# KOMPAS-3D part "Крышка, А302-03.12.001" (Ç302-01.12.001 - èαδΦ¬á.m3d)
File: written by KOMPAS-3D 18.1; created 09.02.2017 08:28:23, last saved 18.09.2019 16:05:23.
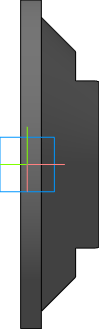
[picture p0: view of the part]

Document properties: Автор: Милов; Организация: Милов; Полное имя файла: D:\Мембранные насосы\Мембранный электропривод\А302-00.00.000 - ASTRA-302 (МЭ200)\3Д ПВХ\А302-01.12.001 - Крышка.m3d

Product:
- Part/product: Крышка  | designation А302-03.12.001
    Материал: Поливинилхлорид (density 1350 kg/m3)
    Масса: 2.71786
    Раздел спецификации: Детали
    Форматы листов документа: 2xA3
    Примечание: @100~)2xA3
    source file: ..\Чертежи Полипропилен\А302-03.12.001 - Крышка.cdw
- Part/product: Крышка  | designation А302-01.12.001
    Материал: Поливинилхлорид (density 1350 kg/m3)
    Масса: 2.45398
    Раздел спецификации: Детали
    Форматы листов документа: 2xA3
    Примечание: @100~)2xA3
    source file: А302-01.12.001 - Крышка.cdw
- Part/product: Крышка  | designation А302-02.12.001
    Материал: Поливинилхлорид (density 1350 kg/m3)
    Масса: 2.64473
    Раздел спецификации: Детали
    Форматы листов документа: 2xA3
    Примечание: @100~)2xA3
    source file: ..\Чертежи ПВХ\А302-02.12.001 - Крышка.cdw, А302-02.00.000 - ASTRA-302 (МЭ200)\А302-02.12.001 - Крышка.cdw

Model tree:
1. Эскиз:24
2. Операция вращения:2
     Угол 1 = 360
3. Эскиз:26  (with: Операция вращения:2)
4. Вырезать элемент выдавливания:1
     Расстояние 1 = 19
5. Массив по концентрической сетке:2  (with: Вырезать элемент выдавливания:1, Эскиз:26)  (12 pattern instances)
     Шаг 2 = 360
6. Фаска:1
     Угол = 45; Длина 1 = 0.5; Длина 2 = 0.5
7. Скругление:3  (with: Операция вращения:2)
     Радиус = 6
8. Эскиз:29
9. Вырезать элемент выдавливания:2
     Расстояние 1 = 47.5
10. Эскиз:30  (with: Операция вращения:2)
11. Вырезать элемент выдавливания:3
     Расстояние 1 = 65
12. Фаска:2  (with: Операция вращения:2)
     Угол = 45; Длина 1 = 0.5; Длина 2 = 0.5
13. Эскиз:32  (with: Операция вращения:2, Вырезать элемент выдавливания:3)
14. Вырезать элемент выдавливания:4
     Расстояние 1 = 51.5
15. Эскиз:33  (with: Скругление:3, Операция вращения:2)
16. Вырезать элемент вращения:1
     Угол 1 = 360
17. Эскиз:35  (with: Операция вращения:2, Скругление:3)
18. Операция выдавливания:1
     Толщина стенки 1 = 2; Расстояние 1 = 1
19. Скругление:4  (with: Операция выдавливания:1)
     Радиус = 1
20. Фаска:3  (with: Вырезать элемент вращения:1)
     Угол = 45; Длина 1 = 1; Длина 2 = 1
21. Эскиз:36
22. Вырезать элемент выдавливания:6
     Расстояние 2 = 10
23. Эскиз:37  (with: Вырезать элемент вращения:1)
24. Вырезать элемент выдавливания:7
     Расстояние 1 = 40; На расстояние 1 = 8
25. Эскиз:38  (with: Операция вращения:2, Вырезать элемент выдавливания:3)
26. Операция выдавливания:2
     Расстояние 2 = 12
27. Эскиз:41  (with: Операция вращения:2, Вырезать элемент выдавливания:3)
28. Операция выдавливания:4
     Расстояние 1 = 8
29. Фаска:5  (with: Операция выдавливания:4)
     Угол = 45; Длина 1 = 0.5; Длина 2 = 0.5
30. Фаска:6  (with: Операция выдавливания:2)
     Угол = 45; Длина 1 = 11; Длина 2 = 11
31. Сечение поверхностью:1  (labels: А302-01.11.000 - Крышка рабочей камеры.a3d)
32. Элемент выдавливания:17  (with: Эскиз:76, Вырезать элемент выдавливания:3)
     Расстояние 2 = 20
33. Элемент выдавливания:18
     Расстояние 2 = 35
34. Фаска:7  (with: Элемент выдавливания:18, Эскиз:78, Операция вращения:2, Элемент выдавливания:32, Элемент выдавливания:33, Эскиз:80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)  (labels: А302-01.11.000 - Крышка рабочей камеры.a3d; А302-01.10.000 - Рабочая камера.a3d)
     Угол = 45; Длина 1 = 11; Длина 2 = 11
35. Элемент выдавливания:19
     Расстояние 1 = 151; Расстояние 2 = 151
36. Фаска:8  (with: Вырезать элемент выдавливания:3)
     Угол = 15; Длина 1 = 3; Длина 2 = 0.803848
37. Фаска:9  (with: Элемент выдавливания:19)  (labels: А302-01.11.000 - Крышка рабочей камеры.a3d)
     Угол = 15; Длина 1 = 3; Длина 2 = 0.803848
38. Элемент выдавливания:20  (with: Эскиз:92)
     Расстояние 2 = 18
39. Элемент выдавливания:21
     Расстояние 2 = 103
40. Фаска:10  (with: Элемент выдавливания:21)
     Угол = 45; Длина 1 = 11; Длина 2 = 11
41. Эскиз:94  (with: Операция вращения:2)
42. Отверстие:1  (with: Операция вращения:2)  (labels: M10x1)
     Глубина выреза = 20; Диаметр отверстия = 8.91747; Угол конуса дна = 118; Расстояние 1 = 44; Расстояние 2 = 35
43. M10x1  (with: Отверстие:1, Операция вращения:2)  (labels: cil0_24705-2004 fine)
     Длина резьбы = 15; Шаг резьбы = 1; Номинальный диаметр резьбы = 10
44. Отверстие:2  (with: Операция вращения:2, M10x1)  (labels: M10x1; cil0_24705-2004 fine)
     Глубина выреза = 20; Диаметр отверстия = 8.91747; Угол конуса дна = 118; Расстояние 1 = -44; Расстояние 2 = 35; Длина резьбы = 15; Шаг резьбы = 1; Номинальный диаметр резьбы = 10
45. Отверстие:3  (with: Операция вращения:2, M10x1)  (labels: M10x1; cil0_24705-2004 fine)
     Глубина выреза = 20; Диаметр отверстия = 8.91747; Угол конуса дна = 118; Расстояние 1 = 44; Длина резьбы = 15; Шаг резьбы = 1; Номинальный диаметр резьбы = 10
46. Отверстие:5  (with: Операция вращения:2, M10x1)  (labels: M10x1; cil0_24705-2004 fine)
     Глубина выреза = 20; Диаметр отверстия = 8.91747; Угол конуса дна = 118; Расстояние 1 = -44; Длина резьбы = 15; Шаг резьбы = 1; Номинальный диаметр резьбы = 10
47. Отверстие:6  (with: Операция вращения:2, M10x1)  (labels: M10x1; cil0_24705-2004 fine)
     Глубина выреза = 20; Диаметр отверстия = 8.91747; Угол конуса дна = 118; Расстояние 1 = 44; Расстояние 2 = -35; Длина резьбы = 15; Шаг резьбы = 1; Номинальный диаметр резьбы = 10
48. Отверстие:7  (with: Операция вращения:2, M10x1)  (labels: M10x1; cil0_24705-2004 fine)
     Глубина выреза = 20; Диаметр отверстия = 8.91747; Угол конуса дна = 118; Расстояние 1 = -44; Расстояние 2 = -35; Длина резьбы = 15; Шаг резьбы = 1; Номинальный диаметр резьбы = 10
49. Эскиз:95  (with: Операция вращения:2, Элемент выдавливания:20)
50. Элемент выдавливания:22
     Расстояние 2 = 3

Expressions: 17.5+10-2.466667-5+4.47; 17.5+10-2.466667
Referenced files in D:\Мембранные насосы\Мембранный электропривод\А302-00.00.000 - ASTRA-302 (МЭ200)\3Д ПВХ\: А302-01.11.000 - Крышка рабочей камеры.a3d, А302-01.10.000 - Рабочая камера.a3d
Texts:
  Линейный размер с обрывом
  Корпус со встроенными стаканами
  Рабочая камера\Крышка рабочей камеры\Корпус со встроенными стаканами
  Рабочая камера\Крышка рабочей камеры\Крышка\Крышка
  Крышка рабочей камеры
  Крышка рабочей камеры\Крышка\Крышка

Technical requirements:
  Gost Type A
